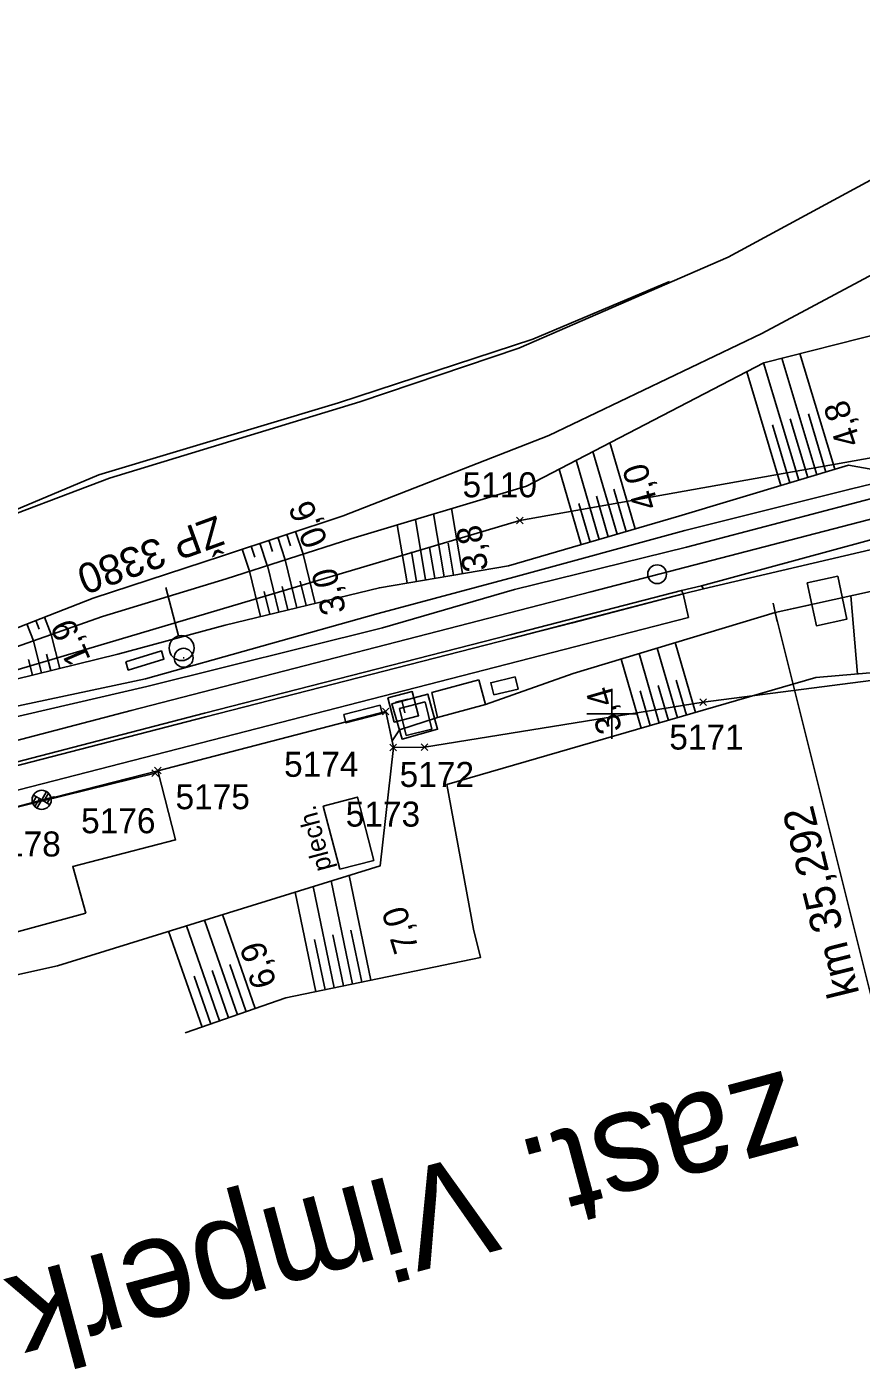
# Model space of a CAD drawing. Extents: x -806456 to -805395, y -1150847 to -1150506.
# Drawn here: x -806146.8 to -806080.1, y -1150752.4 to -1150645.1 of the extents above; entities that cross this region are included whole.
import ezdxf

# ---------------------------------------------------------------- set-up
doc = ezdxf.new("R2010")
doc.units = 0
for name, color, linetype in [('0381KM032-037P - Vrstva 1', 7, 'Continuous'), ('0381KM032-037P - Vrstva 14', 7, 'Continuous'), ('0381KM032-037P - Vrstva 16', 7, 'Continuous'), ('0381KM032-037P - Vrstva 17', 7, 'Continuous'), ('0381KM032-037P - Vrstva 23', 7, 'Continuous'), ('0381KM032-037P - Vrstva 25', 7, 'Continuous'), ('0381KM032-037P - Vrstva 33', 7, 'Continuous'), ('0381KM032-037P - Vrstva 36', 7, 'Continuous'), ('0381KM032-037P - Vrstva 4', 7, 'Continuous'), ('0381KM032-037P - Vrstva 48', 7, 'Continuous'), ('0381KM032-037P - Vrstva 49', 7, 'Continuous'), ('0381KM032-037P - Vrstva 51', 7, 'Continuous'), ('0381KM032-037P - Vrstva 7', 7, 'Continuous'), ('krizky_1000 - Vrstva 1', 7, 'Continuous'), ('szdc - hran DP', 7, 'Continuous'), ('szdc - szdc_cislo', 7, 'Continuous'), ('szdc - szdc_krizek', 7, 'Continuous'), ('vyt_sit - stávající', 7, 'Continuous')]:
    doc.layers.add(name, color=color, linetype=linetype)

msp = doc.modelspace()

# ---------------------------------------------------------------- linework, layer by layer
at = {"layer": '0381KM032-037P - Vrstva 1'}
msp.add_lwpolyline([(-805989.76, -1150661.17), (-806027.03, -1150670.9), (-806064.32, -1150680.56), (-806101.67, -1150690.24), (-806138.44, -1150699.75), (-806158.28, -1150704.94), (-806163.64, -1150706.34), (-806175.38, -1150709.4), (-806186.46, -1150712.29), (-806205.2, -1150717.19), (-806213.26, -1150719.29)], dxfattribs=at)
at = {"layer": '0381KM032-037P - Vrstva 14'}
for p, q in [((-806094.31, -1150690.42), (-806094.43, -1150690.13)), ((-806093.88, -1150692.3), (-806094.31, -1150690.42)), ((-806092.84, -1150689.77), (-806092.67, -1150690)), ((-806161.45, -1150709.69), (-806093.88, -1150692.3))]:
    msp.add_line(p, q, dxfattribs=at)
for points in [[(-806154.89, -1150705.76), (-806154.2, -1150705.57), (-806132.57, -1150699.95), (-806108.13, -1150693.69), (-806094.43, -1150690.13), (-806092.84, -1150689.77), (-806094.43, -1150690.13), (-806108.12, -1150693.69), (-806132.57, -1150699.95), (-806154.2, -1150705.57), (-806154.88, -1150705.76)], [(-806154.82, -1150706.03), (-806154.13, -1150705.84), (-806132.47, -1150700.24), (-806108.06, -1150693.98), (-806094.31, -1150690.42), (-806092.67, -1150690)], [(-806092.67, -1150690), (-806094.31, -1150690.42), (-806103.16, -1150692.72), (-806108.06, -1150693.98)], [(-806154.82, -1150706.03), (-806154.14, -1150705.84), (-806132.47, -1150700.24)]]:
    msp.add_lwpolyline(points, dxfattribs=at)
at = {"layer": '0381KM032-037P - Vrstva 16'}
for q in [(-806113.93, -1150701.24), (-806113.94, -1150701.24)]:
    msp.add_line((-806114.72, -1150698.42), q, dxfattribs=at)
for points in [[(-806114.72, -1150698.42), (-806114.72, -1150698.42), (-806117.58, -1150699.2), (-806117.58, -1150699.2), (-806114.72, -1150698.42)], [(-806117.58, -1150699.2), (-806116.77, -1150702.02), (-806116.77, -1150702.02), (-806117.58, -1150699.2)], [(-806116.77, -1150702.02), (-806113.94, -1150701.24), (-806113.93, -1150701.24), (-806116.77, -1150702.02)]]:
    msp.add_lwpolyline(points, dxfattribs=at)
at = {"layer": '0381KM032-037P - Vrstva 17'}
for points in [[(-806169.28, -1150696.91), (-806165.68, -1150693.97), (-806155.41, -1150686.94), (-806141.03, -1150680.9), (-806121.85, -1150675.14), (-806106.33, -1150670.05), (-806095.39, -1150665.45)], [(-806136.29, -1150704.55), (-806118.08, -1150699.83), (-806117.57, -1150702.15), (-806117.47, -1150702.7)]]:
    msp.add_lwpolyline(points, dxfattribs=at)
at = {"layer": '0381KM032-037P - Vrstva 23'}
for p, q in [((-806110.63, -1150697.29), (-806114.4, -1150698.3)), ((-806110.1, -1150699.27), (-806110.63, -1150697.29)), ((-806116.98, -1150699.59), (-806114.92, -1150699.04)), ((-806114.4, -1150698.3), (-806113.94, -1150700.3)), ((-806116.46, -1150701.73), (-806116.98, -1150699.59)), ((-806113.94, -1150700.3), (-806110.1, -1150699.27))]:
    msp.add_line(p, q, dxfattribs=at)
for points in [[(-806138.87, -1150695.85), (-806138.67, -1150696.5), (-806135.81, -1150695.62), (-806136.01, -1150694.97)], [(-806121.43, -1150700.07), (-806121.26, -1150700.73), (-806118.36, -1150699.98), (-806118.53, -1150699.32)], [(-806142.07, -1150715.95), (-806143.1, -1150712.22), (-806134.89, -1150710.09), (-806136.29, -1150704.55), (-806144.53, -1150706.67), (-806144.58, -1150706.64), (-806151.04, -1150708.34), (-806149.37, -1150714.94), (-806151.84, -1150715.67), (-806151.1, -1150718.4)], [(-806119.02, -1150711.72), (-806121.75, -1150712.41), (-806123.08, -1150707.39), (-806120.35, -1150706.66)]]:
    msp.add_lwpolyline(points, close=True, dxfattribs=at)
msp.add_lwpolyline([(-806114.92, -1150699.04), (-806114.39, -1150701.22), (-806116.46, -1150701.73)], dxfattribs=at)
at = {"layer": '0381KM032-037P - Vrstva 25'}
msp.add_lwpolyline([(-806109.45, -1150698.49), (-806109.68, -1150697.52), (-806107.74, -1150697.05), (-806107.5, -1150698.02), (-806109.45, -1150698.49)], dxfattribs=at)
at = {"layer": '0381KM032-037P - Vrstva 33'}
for p, q in [((-806117.29, -1150699.08), (-806116.32, -1150698.83)), ((-806116.8, -1150698.95), (-806116.55, -1150699.92))]:
    msp.add_line(p, q, dxfattribs=at)
msp.add_lwpolyline([(-806117.9, -1150698.72), (-806115.96, -1150698.22), (-806115.46, -1150700.16), (-806117.4, -1150700.66), (-806117.9, -1150698.72)], dxfattribs=at)
at = {"layer": '0381KM032-037P - Vrstva 36'}
for p, q in [((-806134.65, -1150693.78), (-806135.65, -1150689.91)), ((-806134.4, -1150694.75), (-806134.4, -1150694.75))]:
    msp.add_line(p, q, dxfattribs=at)
msp.add_circle((-806134.4, -1150694.75), 1, dxfattribs=at)
at = {"layer": '0381KM032-037P - Vrstva 4'}
msp.add_line((-806068.97, -1150684.48), (-806092.67, -1150690), dxfattribs=at)
for points in [[(-805920.59, -1150645.08), (-805938.49, -1150646.69), (-805957, -1150650.24), (-805973.18, -1150654.13), (-805996.94, -1150660.52), (-806010.57, -1150664.04), (-806045.29, -1150673.07), (-806070.44, -1150679.45), (-806076.44, -1150680.94), (-806080.95, -1150682.04), (-806094.16, -1150685.34), (-806107.83, -1150689.09)], [(-805923.83, -1150646.61), (-805939.39, -1150648.49), (-805956.78, -1150651.56), (-805972.77, -1150655.27), (-805996.74, -1150661.47), (-806010.38, -1150665.11), (-806045.15, -1150673.98), (-806070.28, -1150680.43), (-806094.02, -1150686.67), (-806107.78, -1150690.05)], [(-806069.3, -1150683.37), (-806092.84, -1150689.77), (-806092.67, -1150690)], [(-806107.83, -1150689.09), (-806118.69, -1150691.97), (-806137.28, -1150697.2), (-806151.73, -1150700.28), (-806152.97, -1150701.48)], [(-806107.78, -1150690.05), (-806118.34, -1150693.12), (-806137.19, -1150697.81), (-806152.97, -1150701.48)]]:
    msp.add_lwpolyline(points, dxfattribs=at)
at = {"layer": '0381KM032-037P - Vrstva 48'}
for p, q in [((-806082.18, -1150680.45), (-806084.96, -1150671.2)), ((-806085.05, -1150681.32), (-806087.87, -1150671.94)), ((-806083.61, -1150680.89), (-806086.41, -1150671.57)), ((-806086.49, -1150681.75), (-806089.22, -1150672.65)), ((-806084.33, -1150681.1), (-806085.74, -1150676.43)), ((-806082.9, -1150680.67), (-806084.29, -1150676.03)), ((-806085.77, -1150681.53), (-806087.16, -1150676.91)), ((-806098.14, -1150685.22), (-806100.15, -1150678.32)), ((-806101.02, -1150686.06), (-806102.86, -1150679.73)), ((-806099.58, -1150685.64), (-806101.51, -1150679.03)), ((-806102.46, -1150686.48), (-806104.22, -1150680.44)), ((-806100.3, -1150685.85), (-806101.24, -1150682.61)), ((-806098.86, -1150685.43), (-806099.85, -1150682.05)), ((-806113.41, -1150689.04), (-806114.26, -1150684.02)), ((-806111.93, -1150688.79), (-806112.81, -1150683.59)), ((-806101.74, -1150686.27), (-806102.64, -1150683.18)), ((-806116.36, -1150689.54), (-806117.16, -1150684.89)), ((-806114.89, -1150689.29), (-806115.71, -1150684.46)), ((-806127.43, -1150686.13), (-806127.13, -1150687.02)), ((-806126.71, -1150685.89), (-806126.12, -1150687.69)), ((-806126, -1150685.66), (-806125.7, -1150686.56)), ((-806125.29, -1150685.42), (-806124.69, -1150687.23)), ((-806129.56, -1150686.84), (-806128.97, -1150688.61)), ((-806128.85, -1150686.6), (-806128.55, -1150687.49)), ((-806128.14, -1150686.37), (-806127.55, -1150688.15)), ((-806123.72, -1150691.17), (-806124.68, -1150687.23)), ((-806115.63, -1150689.42), (-806116.03, -1150687.05)), ((-806114.15, -1150689.16), (-806114.57, -1150686.7)), ((-806112.67, -1150688.91), (-806113.1, -1150686.36)), ((-806126.64, -1150691.88), (-806127.54, -1150688.15)), ((-806125.18, -1150691.52), (-806126.11, -1150687.69)), ((-806128.09, -1150692.23), (-806128.97, -1150688.61)), ((-806124.45, -1150691.34), (-806124.92, -1150689.4)), ((-806127.36, -1150692.05), (-806127.81, -1150690.22)), ((-806125.91, -1150691.7), (-806126.37, -1150689.81)), ((-806080.35, -1150696.82), (-806080.9, -1150690.56)), ((-806146.07, -1150692.54), (-806145.8, -1150693.23)), ((-806145.37, -1150692.27), (-806144.83, -1150693.66)), ((-806146.77, -1150692.81), (-806146.24, -1150694.16)), ((-806144.14, -1150696.38), (-806144.82, -1150693.66)), ((-806145.6, -1150696.74), (-806146.24, -1150694.16)), ((-806094.76, -1150700.32), (-806096.38, -1150694.75)), ((-806093.32, -1150699.9), (-806094.94, -1150694.31)), ((-806146.33, -1150696.92), (-806146.64, -1150695.66)), ((-806144.87, -1150696.56), (-806145.2, -1150695.23)), ((-806097.65, -1150701.15), (-806099.25, -1150695.62)), ((-806096.21, -1150700.74), (-806097.81, -1150695.18)), ((-806095.48, -1150700.53), (-806096.29, -1150697.75)), ((-806094.04, -1150700.11), (-806094.85, -1150697.32)), ((-806096.93, -1150700.94), (-806097.73, -1150698.17)), ((-806119.26, -1150721.31), (-806121.01, -1150712.92)), ((-806122.2, -1150721.92), (-806123.88, -1150713.81)), ((-806120.73, -1150721.61), (-806122.45, -1150713.36)), ((-806123.67, -1150722.22), (-806125.32, -1150714.26)), ((-806128.52, -1150723.57), (-806131.14, -1150716.06)), ((-806131.36, -1150724.56), (-806134.01, -1150716.95)), ((-806129.94, -1150724.07), (-806132.57, -1150716.5)), ((-806120, -1150721.46), (-806120.86, -1150717.3)), ((-806132.77, -1150725.05), (-806135.44, -1150717.39)), ((-806122.93, -1150722.07), (-806123.77, -1150718.05)), ((-806121.46, -1150721.76), (-806122.32, -1150717.68)), ((-806130.65, -1150724.31), (-806131.97, -1150720.52)), ((-806129.23, -1150723.82), (-806130.54, -1150720.05)), ((-806132.07, -1150724.81), (-806133.39, -1150720.99))]:
    msp.add_line(p, q, dxfattribs=at)
at = {"layer": '0381KM032-037P - Vrstva 49'}
for points in [[(-806106.83, -1150681.79), (-806087.86, -1150671.94), (-806068.49, -1150667.04), (-806060.84, -1150659.9)], [(-806070.76, -1150678.42), (-806076.44, -1150680.94), (-806081.09, -1150680.13), (-806094.64, -1150684.2), (-806108.26, -1150688.17)], [(-806042.38, -1150685.77), (-806037.14, -1150679.5), (-806067.5, -1150691.31), (-806072.52, -1150696.14), (-806083.69, -1150697.11)], [(-806106.83, -1150681.79), (-806120.86, -1150686.01), (-806130.84, -1150689.2), (-806140.72, -1150692.22), (-806149.98, -1150695.47), (-806155.41, -1150698.65)], [(-806160.94, -1150702.04), (-806159.44, -1150700.5), (-806157.04, -1150698.34), (-806150.42, -1150694.24), (-806141.48, -1150690.75), (-806131.12, -1150687.36), (-806121.48, -1150684.16)], [(-806068.97, -1150684.48), (-806072.55, -1150688.73), (-806086.94, -1150691.89)], [(-806155.86, -1150700.93), (-806155.37, -1150700.64), (-806154.96, -1150699.45), (-806154.58, -1150699.23), (-806153.89, -1150698.71), (-806149.38, -1150697.67), (-806139.49, -1150695.22), (-806130.93, -1150692.92), (-806118.59, -1150689.92), (-806108.26, -1150688.17)], [(-806086.94, -1150691.89), (-806103.09, -1150696.78), (-806110.1, -1150699.27), (-806113.94, -1150700.3), (-806116.98, -1150701.29), (-806117.57, -1150702.15), (-806117.47, -1150702.7), (-806118.52, -1150712.15), (-806144.33, -1150720.15), (-806155.42, -1150722.6), (-806156.37, -1150719.96), (-806156.92, -1150718.66), (-806157.56, -1150717.45), (-806160.48, -1150717.28), (-806160.29, -1150717.98), (-806160.2, -1150718.76), (-806166.07, -1150720.05), (-806166.41, -1150718.42)], [(-806083.69, -1150697.11), (-806113.19, -1150705.65), (-806111.06, -1150717.22), (-806110.51, -1150719.49), (-806126.08, -1150722.72), (-806134.13, -1150725.52)]]:
    msp.add_lwpolyline(points, dxfattribs=at)
at = {"layer": '0381KM032-037P - Vrstva 51'}
for points in [[(-806140.16, -1150681.15), (-806120.15, -1150675.05), (-806107.44, -1150670.76), (-806090.7, -1150663.5), (-806064.75, -1150649.45)], [(-806121.48, -1150684.16), (-806105.03, -1150677.76), (-806088.01, -1150669.6), (-806061.17, -1150655.26)], [(-806195.22, -1150723.44), (-806183.65, -1150718.08), (-806179.48, -1150714.68), (-806176.79, -1150711.84), (-806173.36, -1150707), (-806168.38, -1150700.15), (-806163.11, -1150693.21), (-806157.22, -1150688.72), (-806150.87, -1150685.21), (-806140.16, -1150681.15)], [(-806194.18, -1150731.58), (-806186.23, -1150728.98), (-806178.59, -1150724.92), (-806174.21, -1150722.04), (-806171.13, -1150719.06), (-806168.37, -1150714.46), (-806165.45, -1150708.87), (-806162.71, -1150704.24), (-806160.94, -1150702.04), (-806159.44, -1150700.5), (-806157.04, -1150698.34), (-806150.42, -1150694.24), (-806141.48, -1150690.75), (-806131.12, -1150687.36), (-806121.48, -1150684.16)]]:
    msp.add_lwpolyline(points, dxfattribs=at)
at = {"layer": '0381KM032-037P - Vrstva 7'}
for p, q in [((-806087.1, -1150691.15), (-806086.78, -1150692.62)), ((-806086.94, -1150691.89), (-806077.64, -1150729.17))]:
    msp.add_line(p, q, dxfattribs=at)
msp.add_lwpolyline([(-806086.94, -1150691.89), (-806084.01, -1150691.25), (-806083.64, -1150692.96), (-806081.2, -1150692.43), (-806081.94, -1150689.01), (-806084.38, -1150689.54), (-806084.01, -1150691.25)], dxfattribs=at)
msp.add_circle((-806096.38, -1150688.84), 0.75, dxfattribs=at)
at = {"layer": 'krizky_1000 - Vrstva 1'}
for points in [[(-806100, -1150698), (-806100, -1150702)], [(-806102, -1150700), (-806098, -1150700)]]:
    msp.add_lwpolyline(points, dxfattribs=at)
at = {"layer": 'szdc - hran DP'}
for p, q in [((-806107.35, -1150684.54), (-806073.91, -1150678.57)), ((-806152.11, -1150697.83), (-806107.35, -1150684.54)), ((-806066.55, -1150695.68), (-806092.7, -1150699.08)), ((-806092.7, -1150699.08), (-806114.99, -1150702.66)), ((-806118.08, -1150699.83), (-806136.29, -1150704.55)), ((-806117.47, -1150702.7), (-806118.08, -1150699.83)), ((-806114.99, -1150702.66), (-806117.47, -1150702.7)), ((-806136.51, -1150704.75), (-806151.02, -1150708.33)), ((-806136.29, -1150704.55), (-806136.51, -1150704.75))]:
    msp.add_line(p, q, dxfattribs=at)
at = {"layer": 'szdc - szdc_krizek'}
for p, q in [((-806107.08, -1150684.8), (-806107.62, -1150684.28)), ((-806107.62, -1150684.8), (-806107.08, -1150684.28)), ((-806092.44, -1150699.34), (-806092.97, -1150698.81)), ((-806092.97, -1150699.34), (-806092.44, -1150698.81)), ((-806117.82, -1150700.09), (-806118.35, -1150699.56)), ((-806118.35, -1150700.09), (-806117.82, -1150699.56)), ((-806117.21, -1150702.97), (-806117.74, -1150702.44)), ((-806117.74, -1150702.97), (-806117.21, -1150702.44)), ((-806114.72, -1150702.93), (-806115.26, -1150702.4)), ((-806115.26, -1150702.93), (-806114.72, -1150702.4)), ((-806136.03, -1150704.81), (-806136.56, -1150704.28)), ((-806136.56, -1150704.81), (-806136.03, -1150704.28)), ((-806136.24, -1150705.02), (-806136.78, -1150704.49)), ((-806136.78, -1150705.02), (-806136.24, -1150704.49))]:
    msp.add_line(p, q, dxfattribs=at)
at = {"layer": 'vyt_sit - stávající'}
for p, q in [((-806134.29, -1150695.52), (-806134.19, -1150695.52)), ((-806146.25, -1150706.5), (-806145.59, -1150706.88)), ((-806145.59, -1150706.88), (-806145.2, -1150706.22)), ((-806145.41, -1150706.99), (-806145.04, -1150706.36)), ((-806146.31, -1150707.13), (-806146.02, -1150706.63)), ((-806146.13, -1150707.42), (-806145.76, -1150706.78)), ((-806145.59, -1150706.88), (-806145.98, -1150707.54)), ((-806144.93, -1150707.27), (-806145.59, -1150706.88)), ((-806145.15, -1150707.14), (-806144.86, -1150706.65))]:
    msp.add_line(p, q, dxfattribs=at)
for centre, radius in [((-806134.24, -1150695.52), 0.756), ((-806145.59, -1150706.88), 0.764)]:
    msp.add_circle(centre, radius, dxfattribs=at)
for radius, start, end in [(0.764, 149.1827, 239.5007), (0.765, 329.8715, 59.765)]:
    msp.add_arc((-806145.59, -1150706.88), radius, start, end, dxfattribs=at)

# ---------------------------------------------------------------- texts
at = {"layer": '0381KM032-037P - Vrstva 23'}
for s, height, rotation, p in [('plech.', 1.5, 104.8456, (-806122.36, -1150712.38)), ('zast. Vimperk', 8, 195, (-806086.07, -1150728.44))]:
    msp.add_text(s, height=height, rotation=rotation, dxfattribs=at).set_placement(p)
at = {"layer": '0381KM032-037P - Vrstva 48'}
for s, rotation, p in [('4,8', 108.036, (-806080.07, -1150678.31)), ('4,0', 106.2287, (-806096.24, -1150683.39)), ('0,6', 111.6516, (-806122.68, -1150686.22)), ('3,8', 99.6413, (-806109.88, -1150688.46)), ('3,0', 103.6676, (-806121.23, -1150691.81)), ('1,9', 113.3162, (-806141.64, -1150695.64)), ('3,4', 106.1463, (-806099.15, -1150701.26)), ('7,0', 107.0974, (-806115.43, -1150718.78)), ('6,9', 106.8709, (-806126.79, -1150721.6))]:
    msp.add_text(s, height=2, rotation=rotation, dxfattribs=at).set_placement(p)
at = {"layer": '0381KM032-037P - Vrstva 7'}
msp.add_text('km 35,292', height=2.5, rotation=103.9101, dxfattribs=at).set_placement((-806080.2, -1150722.36))
at = {"layer": 'szdc - szdc_cislo'}
for s, p in [('5110', (-806111.94, -1150682.69)), ('5171', (-806095.41, -1150702.86)), ('5174', (-806126.21, -1150705.04)), ('5172', (-806116.97, -1150705.85)), ('5175', (-806134.89, -1150707.63)), ('5176', (-806142.44, -1150709.55)), ('5173', (-806121.28, -1150709.02)), ('5178', (-806150.01, -1150711.41))]:
    msp.add_text(s, height=2, dxfattribs=at).set_placement(p)
at = {"layer": 'vyt_sit - stávající'}
msp.add_text('ŽP 3380', height=2.4, rotation=200, dxfattribs=at).set_placement((-806131.56, -1150684.11))

doc.saveas('drawing.dxf')
